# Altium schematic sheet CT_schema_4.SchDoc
size 283 x 174 mm
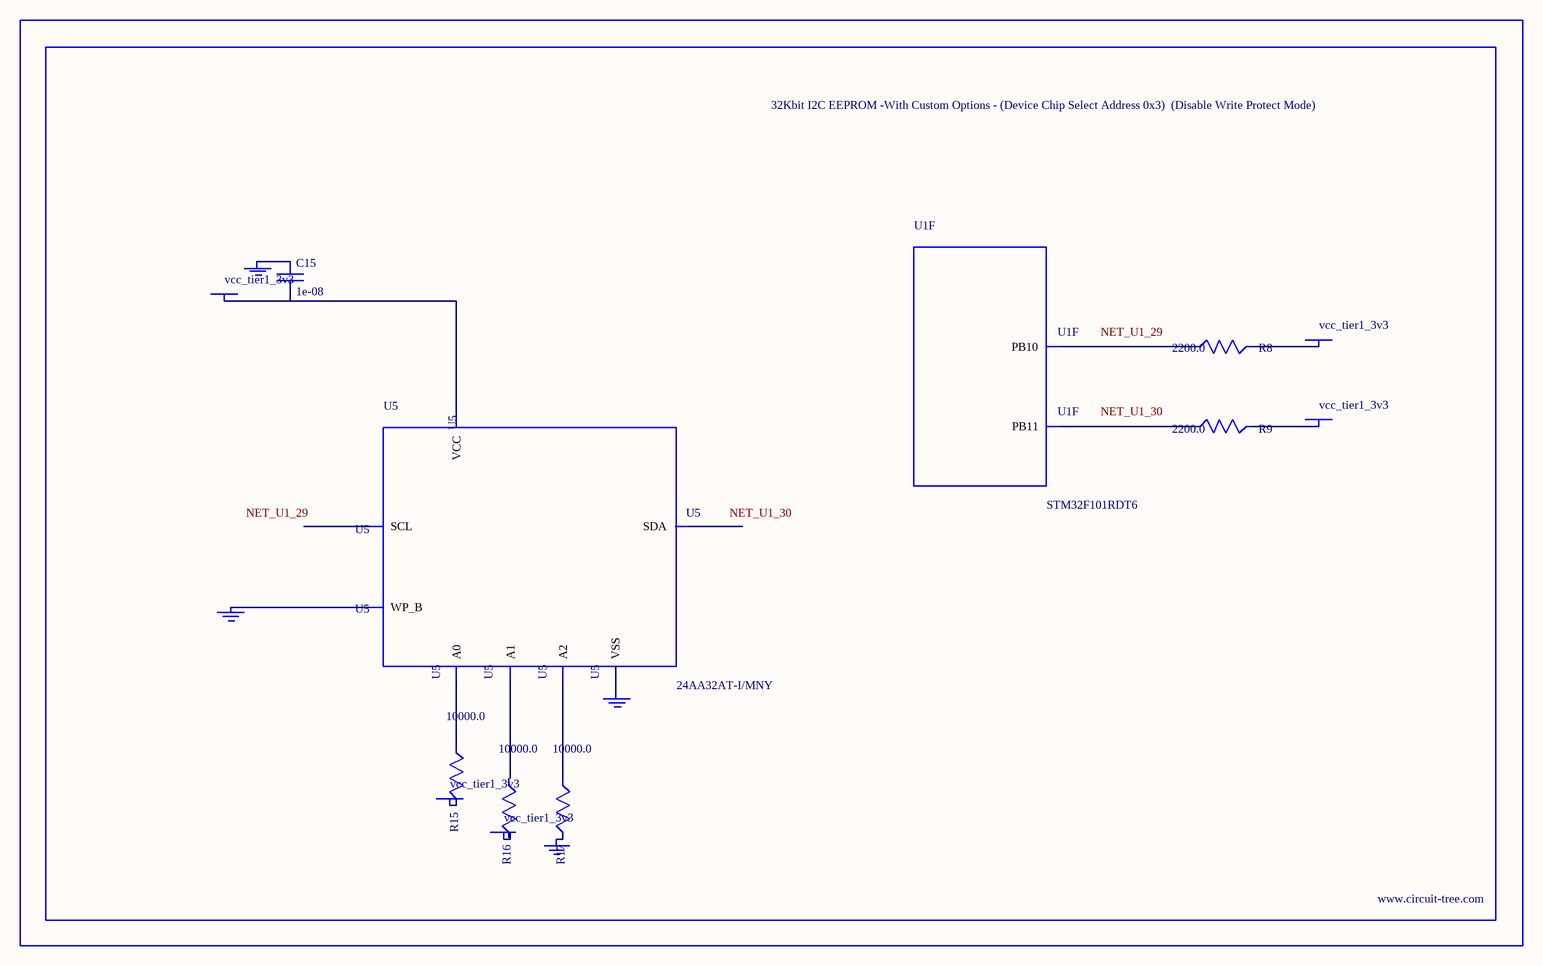
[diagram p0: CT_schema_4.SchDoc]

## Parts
BORDER3  (no value)
C15  1e-08  [C0402]
GND_INSTANCE_3_0  (no value)
GND_INSTANCE_3_1  (no value)
GND_INSTANCE_3_2  (no value)
GND_INSTANCE_3_3  (no value)
POWER_INSTANCE_3_0  vcc_tier1_3v3
POWER_INSTANCE_3_1  vcc_tier1_3v3
POWER_INSTANCE_3_2  vcc_tier1_3v3
POWER_INSTANCE_3_3  vcc_tier1_3v3
POWER_INSTANCE_3_4  vcc_tier1_3v3
R8  2200.0  [R0603]
R9  2200.0  [R0603]
R15  10000.0  [R0603]
R16  10000.0  [R0603]
R17  10000.0  [R0603]
U1  STM32F101RDT6  [LQFP64]  (part F of 7)
U5  24AA32AT-I/MNY  [TDFN-8/6MM]

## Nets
NetC15_1: C15.1 GND_INSTANCE_3_2.0(GND)
NetC15_2: C15.2 POWER_INSTANCE_3_2.0(PWR) U5.8(VCC)
NetGND_INSTANCE_3_0_0: GND_INSTANCE_3_0.0(GND) R17.2
NetGND_INSTANCE_3_1_0: GND_INSTANCE_3_1.0(GND) U5.7(WP_B)
NetGND_INSTANCE_3_3_0: GND_INSTANCE_3_3.0(GND) U5.4(VSS)
NetPOWER_INSTANCE_3_0_0: POWER_INSTANCE_3_0.0(PWR) R15.2
NetPOWER_INSTANCE_3_3_0: POWER_INSTANCE_3_3.0(PWR) R8.2
NetPOWER_INSTANCE_3_4_0: POWER_INSTANCE_3_4.0(PWR) R9.2
NetR8_1: R8.1 U1.29(PB10)
NetR9_1: R9.1 U1.30(PB11)
NetR15_1: R15.1 U5.1(A0)
NetR17_1: R17.1 U5.3(A2)

Not connected (* = marked no-connect by the designer): POWER_INSTANCE_3_1 0(PWR); R16 1 2; U5 2(A1) 5(SDA) 6(SCL)

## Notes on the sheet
- Labels drawn without touching a wire or pin: NET_U1_29, NET_U1_30

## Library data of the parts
BORDER3 = BORDER_PAGE3
C15 = C0402C103K3RAC
GND_INSTANCE_3_0-GND_INSTANCE_3_3 = GND
POWER_INSTANCE_3_0-POWER_INSTANCE_3_4 = PWR
R8 R9 = RC0603JR-072K2L
R15-R17 = RC0603JR-0710KL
